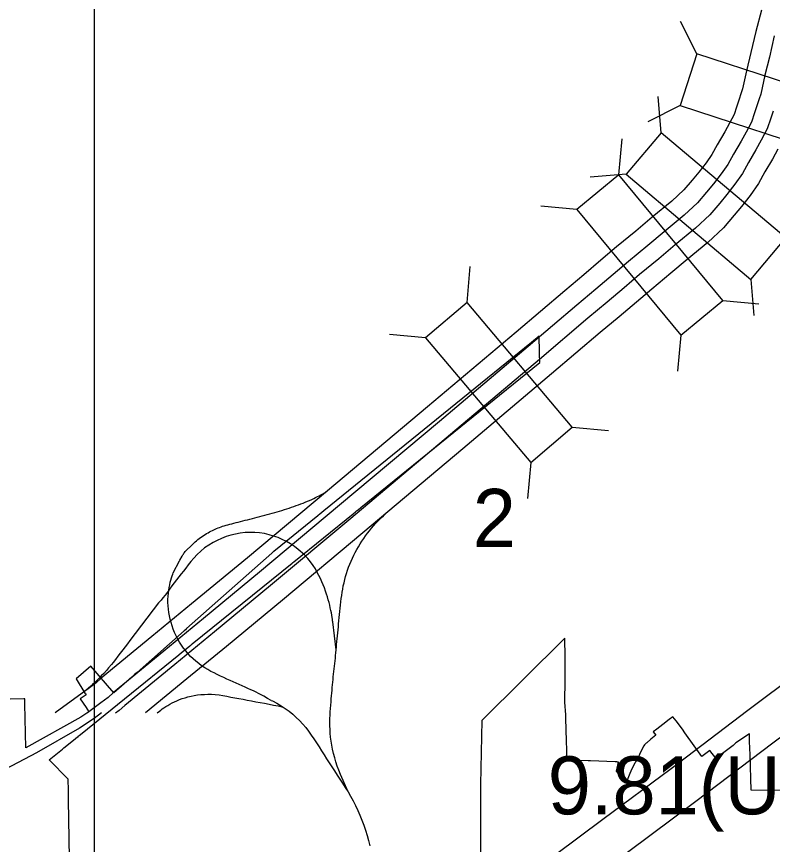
# Model space of a CAD drawing. Extents: x 1127717 to 1741049, y 2026793 to 2244711.
# Drawn here: x 1240828 to 1243581, y 2142172 to 2145187 of the extents above; entities that cross this region are included whole.
import ezdxf

# ---------------------------------------------------------------- set-up
doc = ezdxf.new("R2010")
doc.units = 0
for name, color, linetype in [('10', 7, 'Continuous'), ('15', 7, 'Continuous'), ('20', 7, 'Continuous'), ('30', 7, 'Continuous'), ('58', 7, 'Continuous'), ('6', 7, 'Continuous')]:
    doc.layers.add(name, color=color, linetype=linetype)

msp = doc.modelspace()

# ---------------------------------------------------------------- linework, layer by layer
at = {"layer": '10'}
for points in [[(1241669.2, 2143354.5), (1241677.9, 2143356.8), (1241686.8, 2143359.1), (1241695.7, 2143361.4), (1241704.7, 2143363.7), (1241713.8, 2143366.1), (1241722.8, 2143368.4), (1241731.9, 2143370.8), (1241740.9, 2143373.2), (1241750, 2143375.6), (1241759.1, 2143378), (1241768.1, 2143380.5), (1241777.1, 2143383), (1241786, 2143385.7), (1241794.7, 2143388.5), (1241803.3, 2143391.2), (1241811.9, 2143394), (1241820.5, 2143396.8), (1241829.1, 2143399.8), (1241837.6, 2143402.8), (1241846.1, 2143405.8), (1241854.5, 2143409), (1241862.9, 2143412.1), (1241871.2, 2143415.2), (1241879.4, 2143418.4), (1241887.4, 2143421.6), (1241895.2, 2143425), (1241902.8, 2143428.4), (1241910.1, 2143431.8), (1241917.2, 2143435.3), (1241923.9, 2143438.6), (1241930, 2143441.8), (1241935.6, 2143444.7), (1241956.7, 2143456.5)], [(1241755.7, 2142696.3), (1241742.4, 2142704), (1241729, 2142711.5), (1241718.5, 2142716.7), (1241709.6, 2142721.7), (1241700.4, 2142726.4), (1241690.8, 2142731), (1241680.8, 2142735.5), (1241670.6, 2142740.1), (1241660.2, 2142744.8), (1241649.6, 2142749.5), (1241638.8, 2142754.3), (1241627.9, 2142759.2), (1241616.7, 2142764.1), (1241605.5, 2142769.1), (1241594.1, 2142774.2), (1241582.5, 2142779.5), (1241570.9, 2142784.9), (1241559.2, 2142790.5), (1241547.7, 2142796.3), (1241536, 2142802.3), (1241524.5, 2142808.7), (1241513.2, 2142815.5), (1241502, 2142822.8), (1241491.3, 2142830.7), (1241481, 2142839.1), (1241471.3, 2142847.8), (1241461.9, 2142856.8), (1241453, 2142866.4), (1241444.5, 2142876.4), (1241436.5, 2142886.7), (1241428.9, 2142897.4), (1241421.9, 2142908.5), (1241415.3, 2142919.8), (1241409.2, 2142931.4), (1241403.7, 2142943.3), (1241398.8, 2142955.4), (1241394.5, 2142967.7), (1241390.7, 2142980.1), (1241387.5, 2142992.4), (1241384.8, 2143004.6), (1241382.6, 2143016.8), (1241381, 2143028.8), (1241380, 2143040.8), (1241379.5, 2143052.6), (1241379.5, 2143064.4), (1241380, 2143075.9), (1241380.9, 2143087.1), (1241382.3, 2143097.8), (1241383.9, 2143107.8), (1241385.8, 2143117.4), (1241387.9, 2143126.5), (1241390, 2143134.9), (1241392.2, 2143142.6), (1241394.5, 2143149.6), (1241396.8, 2143155.7), (1241398.9, 2143161), (1241421.1, 2143204.5), (1241422.2, 2143207), (1241431.1, 2143221.9), (1241432.5, 2143224.2), (1241433.9, 2143226.5), (1241435.7, 2143229.2), (1241437.7, 2143232.1), (1241439.9, 2143235.1), (1241442.4, 2143238.3), (1241468.8, 2143264.6), (1241473.4, 2143269.2), (1241478.2, 2143273.7), (1241483, 2143278), (1241488, 2143282.2), (1241493.2, 2143286.2), (1241498.5, 2143290), (1241503.8, 2143293.7), (1241509.2, 2143297.3), (1241514.5, 2143300.7), (1241519.9, 2143304), (1241525.3, 2143307.1), (1241530.6, 2143310), (1241535.9, 2143312.8), (1241541.1, 2143315.4), (1241546.2, 2143317.9), (1241551.3, 2143320.3), (1241556.4, 2143322.5), (1241561.7, 2143324.5), (1241567.1, 2143326.5), (1241572.7, 2143328.5), (1241578.6, 2143330.5), (1241584.7, 2143332.4), (1241591.2, 2143334.3), (1241598, 2143336.1), (1241605, 2143337.9), (1241612.3, 2143339.8), (1241619.9, 2143341.8), (1241627.6, 2143344), (1241635.6, 2143346.1), (1241643.7, 2143348.2), (1241652, 2143350.3), (1241660.5, 2143352.4), (1241669.2, 2143354.5)], [(1242035.1, 2142363.5), (1242007.7, 2142426.9), (1242001.7, 2142441.9), (1241996.2, 2142457.2), (1241991.2, 2142472.6), (1241986.8, 2142487.9), (1241982.8, 2142503.2), (1241979.2, 2142518.3), (1241976.1, 2142533.2), (1241973.7, 2142547.9), (1241971.8, 2142562.5), (1241970.5, 2142576.7), (1241969.7, 2142590.7), (1241969.2, 2142604.1), (1241969.1, 2142617.3), (1241969.2, 2142630.2), (1241969.7, 2142642.9), (1241970.4, 2142655.3), (1241971.3, 2142667.5), (1241972.3, 2142679.4), (1241973.4, 2142691), (1241974.3, 2142702.2), (1241975.2, 2142712.9), (1241976.1, 2142723.2), (1241976.9, 2142733.3), (1241977.8, 2142743.2), (1241978.7, 2142752.9), (1241979.6, 2142762.7), (1241980.6, 2142772.4), (1241981.6, 2142782.1), (1241982.7, 2142791.9), (1241983.8, 2142801.6), (1241984.9, 2142811.4), (1241986, 2142821.2), (1241987, 2142830.9), (1241988, 2142840.7), (1241989, 2142850.6), (1241989.9, 2142860.4), (1241990.8, 2142870.3), (1241991.7, 2142880.2), (1241992.7, 2142890.2), (1241993.6, 2142900.3), (1241994.6, 2142910.6), (1241995.6, 2142921), (1241996.6, 2142931.6), (1241997.7, 2142942.3), (1241998.8, 2142953.1), (1241999.9, 2142964.1), (1242001, 2142975.2), (1242002.2, 2142986.5), (1242003.3, 2142997.8), (1242004.6, 2143009.1), (1242005.8, 2143020.5), (1242007, 2143032.1), (1242008.2, 2143043.7), (1242010.7, 2143067), (1242012.1, 2143078.7), (1242013.8, 2143090.3), (1242015.7, 2143101.9), (1242017.9, 2143113.4), (1242020.5, 2143124.9), (1242023.2, 2143136.3), (1242026.3, 2143147.7), (1242029.7, 2143159.1), (1242033.4, 2143170.3), (1242037.4, 2143181.5), (1242041.7, 2143192.5), (1242046.3, 2143203.4), (1242051.1, 2143214.1), (1242056.1, 2143224.8), (1242061.4, 2143235.3), (1242067, 2143245.8), (1242072.9, 2143256), (1242079, 2143266.1), (1242085.5, 2143276.1), (1242092.2, 2143285.9), (1242099, 2143295.6), (1242106, 2143305.1), (1242113.2, 2143314.3), (1242120.6, 2143323.3), (1242128, 2143332), (1242135.5, 2143340.3), (1242142.7, 2143348), (1242149.9, 2143355.2), (1242157.1, 2143362), (1242164.1, 2143368.4), (1242173.3, 2143377.3)], [(1241991.7, 2142880.2), (1241979.5, 2142982.2), (1241978.9, 2142986.6), (1241978.2, 2142991.9), (1241977.3, 2142998.7), (1241976, 2143006.6), (1241974.5, 2143014.9), (1241972.7, 2143023.8), (1241970.7, 2143033.3), (1241968.4, 2143042.8), (1241965.9, 2143052.7), (1241963.1, 2143062.8), (1241960, 2143073.2), (1241956.6, 2143083.9), (1241952.9, 2143094.7), (1241948.9, 2143105.9), (1241944.3, 2143117.4), (1241939.5, 2143128.7), (1241934.4, 2143139.9), (1241929, 2143151.1), (1241923.1, 2143162.7), (1241916.2, 2143175.2), (1241908, 2143188.2), (1241898.6, 2143201.3), (1241888.3, 2143213.7), (1241876.6, 2143226.2), (1241854, 2143246.5), (1241839.8, 2143257.3), (1241825.4, 2143266.8), (1241810.5, 2143275.3), (1241795.5, 2143282.7), (1241780.2, 2143289.2), (1241764.3, 2143294.9), (1241747.7, 2143299.8), (1241730.5, 2143303.7), (1241713.1, 2143306.4), (1241695.4, 2143308), (1241677.7, 2143308.3), (1241660.1, 2143307.5), (1241642.3, 2143305.5), (1241625.1, 2143302.3), (1241608.3, 2143298.2), (1241591.5, 2143293), (1241574.7, 2143286.6), (1241559, 2143279.3), (1241543.9, 2143271.5), (1241528.5, 2143262.3), (1241513.1, 2143251.6), (1241498.6, 2143239.7), (1241485.6, 2143227.4), (1241473.4, 2143214.7), (1241462.4, 2143201.8), (1241452.8, 2143189.7), (1241444.1, 2143178.3), (1241435.9, 2143167.6), (1241427.6, 2143156.9), (1241419.2, 2143146), (1241410.9, 2143135.1), (1241402.4, 2143124.1), (1241394, 2143113.1), (1241385.5, 2143102.1), (1241377.2, 2143091.2), (1241368.7, 2143080.2), (1241360.7, 2143069.8), (1241354.4, 2143061.9), (1241344.7, 2143051.7), (1241240.9, 2142914.1), (1241232.2, 2142902.8), (1241223.5, 2142891.6), (1241214.7, 2142880.3), (1241205.9, 2142868.9), (1241197.1, 2142857.5), (1241188.2, 2142846), (1241179.4, 2142834.6), (1241173.4, 2142826.9), (1241163.5, 2142815.1), (1241155.3, 2142805.9), (1241145.7, 2142795), (1241136.7, 2142785.5), (1241128.7, 2142777.3), (1241120.3, 2142768.4), (1241111.6, 2142760.2), (1241104.3, 2142753.8), (1241098.5, 2142748.7), (1241088.6, 2142740), (1241076.7, 2142730)], [(1243898.9, 2143085.3), (1243769, 2142912), (1243734.4, 2142862.7), (1243709.9, 2142830.5), (1243698.6, 2142819.4), (1243674.7, 2142797.3), (1243491.4, 2142660.2), (1243211.8, 2142447.8), (1242963, 2142262.3), (1242790.6, 2142134.3), (1242584.6, 2141983.8), (1242522, 2141937.1), (1242493.2, 2141917.6), (1242476.6, 2141902.6), (1242450.7, 2141877.1), (1242424.4, 2141844.8), (1242306.6, 2141708.8), (1242245, 2141634.7), (1242230.2, 2141613.9)], [(1244018.9, 2142995.3), (1243890.4, 2142823.9), (1243855.5, 2142774.2), (1243822.8, 2142731.1), (1243802.2, 2142710.9), (1243771, 2142681.9), (1243581.7, 2142540.4), (1243302, 2142328), (1243052.6, 2142142), (1242879.6, 2142013.5), (1242673.7, 2141863.1), (1242608.9, 2141814.8), (1242585.9, 2141799.2), (1242579.4, 2141793.3), (1242561.8, 2141776), (1242539.3, 2141748.4), (1242421, 2141611.8), (1242363.9, 2141543.1), (1242339.2, 2141508.4), (1242308.1, 2141461.2), (1242275.8, 2141417), (1242253.4, 2141381.2), (1242227.4, 2141356.2)], [(1241340.3, 2142650.7), (1241348.1, 2142657.2), (1241353, 2142661.2), (1241358.6, 2142665.4), (1241364.8, 2142669.7), (1241371.5, 2142674), (1241378.7, 2142678.4), (1241386.4, 2142682.8), (1241394.6, 2142687.2), (1241403.1, 2142691.4), (1241412.1, 2142695.4), (1241421.5, 2142699.3), (1241431.3, 2142702.9), (1241441.6, 2142706.2), (1241452.4, 2142709.2), (1241463.6, 2142711.9), (1241475.2, 2142714.2), (1241487.1, 2142716.2), (1241499.5, 2142717.6), (1241512.1, 2142718.5), (1241525.1, 2142718.9), (1241538.4, 2142718.6), (1241551.9, 2142717.8), (1241565.7, 2142716.2), (1241579.7, 2142714.1), (1241594, 2142711.6), (1241608.4, 2142708.8), (1241623.1, 2142706), (1241638, 2142703.2), (1241653.1, 2142700.4), (1241668.3, 2142697.6), (1241683.8, 2142694.7), (1241699.5, 2142691.8), (1241715.3, 2142688.9), (1241731.5, 2142685.9), (1241747.7, 2142682.9), (1241764.2, 2142679.7), (1241780.6, 2142676.3), (1241799.1, 2142672.2)], [(1241755.7, 2142696.3), (1241760, 2142694.3), (1241776, 2142686.1), (1241791.7, 2142677), (1241806.7, 2142667.3), (1241820.8, 2142657.1), (1241834.2, 2142646.3), (1241846.8, 2142634.8), (1241858.8, 2142622.8), (1241870.2, 2142610.3), (1241881, 2142597.3), (1241891.4, 2142583.9), (1241901.5, 2142570.2), (1241911.1, 2142556.1), (1241920.4, 2142541.7), (1241929.5, 2142527.3), (1241938.6, 2142512.8), (1241947.7, 2142498.2), (1241956.9, 2142483.7), (1241966.4, 2142469.1), (1241976, 2142454.4), (1241985.7, 2142439.6), (1241995.4, 2142424.8), (1242005.3, 2142409.9), (1242015.4, 2142394.8), (1242025.3, 2142379.3), (1242035.1, 2142363.5), (1242044.5, 2142347.3), (1242053.6, 2142330.6), (1242062.2, 2142313.5), (1242070.3, 2142296), (1242078.1, 2142278.3), (1242085.4, 2142260.2), (1242092.1, 2142241.9), (1242098.5, 2142223.4), (1242104.4, 2142204.8), (1242109.8, 2142186), (1242114.7, 2142167.1)]]:
    msp.add_lwpolyline(points, dxfattribs=at)
at = {"layer": '15'}
for points in [[(1243540.2, 2145209.6), (1243519.8, 2145132.9), (1243502.5, 2145055.4), (1243485.7, 2144989.1), (1243471.7, 2144923.2), (1243466.6, 2144908.9), (1243457.9, 2144882.2), (1243450.1, 2144857.1), (1243440.8, 2144830), (1243424.3, 2144798.5), (1243406.7, 2144766.8), (1243379.1, 2144719.6), (1243360.2, 2144684.8), (1243338.7, 2144654.7), (1243312.3, 2144620.4), (1243288.3, 2144591.5), (1243258, 2144555.6), (1243213.8, 2144514.8), (1243142.4, 2144455.8), (1243082.7, 2144405.4), (1243012.7, 2144347.6), (1242956, 2144299.5), (1242893.7, 2144246.7), (1242824.2, 2144188.4), (1242647.2, 2144037.9), (1242324, 2143765.3), (1241960.4, 2143459.6), (1241669.3, 2143215.9), (1241465.4, 2143047.7), (1241320.9, 2142929.1), (1241136.6, 2142777.4), (1241118, 2142760.7), (1241093.8, 2142742.6), (1240969.3, 2142650.9)], [(1243586.6, 2145116.6), (1243569.4, 2145039.5), (1243552.7, 2144973.5), (1243538, 2144904.6), (1243531.7, 2144886.8), (1243523.4, 2144861.4), (1243515.4, 2144835.7), (1243504.1, 2144802.8), (1243484.8, 2144765.8), (1243466.4, 2144732.7), (1243439, 2144685.9), (1243418.6, 2144648.2), (1243393.9, 2144613.7), (1243365.9, 2144577.4), (1243341, 2144547.4), (1243307.8, 2144508.1), (1243259.1, 2144463), (1243186.4, 2144403), (1243126.7, 2144352.7), (1243056.8, 2144294.9), (1243000.5, 2144247.1), (1242938, 2144194.2), (1242868.6, 2144135.9), (1242691.6, 2143985.4), (1242368.3, 2143712.7), (1242004.6, 2143406.9), (1241713.3, 2143163.1), (1241509.1, 2142994.6), (1241364.5, 2142876), (1241181.5, 2142725.3), (1241161.7, 2142707.5), (1241134.7, 2142687.3), (1241086, 2142651.5)], [(1243583, 2144842.4), (1243574.8, 2144816.3), (1243561.7, 2144778), (1243539.8, 2144736.2), (1243520.7, 2144701.7), (1243493.5, 2144655.2), (1243471.7, 2144615), (1243444.1, 2144576.4), (1243414.7, 2144538.3), (1243388.9, 2144507.3), (1243353.1, 2144464.8), (1243300.2, 2144415.9), (1243226.4, 2144355), (1243166.8, 2144304.7), (1243097, 2144247), (1243040.9, 2144199.4), (1242978.3, 2144146.4), (1242908.9, 2144088.2), (1242732, 2143937.7), (1242408.5, 2143664.9), (1242044.8, 2143359.1), (1241753.2, 2143115), (1241548.8, 2142946.4), (1241404.2, 2142827.7), (1241222.3, 2142678), (1241201.4, 2142659.2), (1241189, 2142649.8)], [(1243600.4, 2144703.6), (1243580.4, 2144667.7), (1243553.4, 2144621.4), (1243530.1, 2144578.5), (1243499.3, 2144535.4), (1243468.4, 2144495.4), (1243441.6, 2144463.1), (1243402.9, 2144417.2), (1243345.5, 2144364.1), (1243270.5, 2144302.2), (1243210.9, 2144251.9), (1243141.1, 2144194.3), (1243085.3, 2144146.9), (1243022.6, 2144093.8), (1242953.3, 2144035.7), (1242776.5, 2143885.2), (1242452.8, 2143612.3), (1242089, 2143306.4), (1241797.1, 2143062.1), (1241592.5, 2142893.3), (1241447.8, 2142774.6), (1241297.4, 2142650.7)], [(1241138, 2142650.9), (1241111, 2142631.1), (1241056.9, 2142595.5), (1240901.2, 2142506), (1240717.4, 2142410)]]:
    msp.add_lwpolyline(points, dxfattribs=at)
at = {"layer": '20'}
for p, q in [((1243305.7, 2145051), (1243245.9, 2145168.6)), ((1243175.9, 2144763.9), (1243164.8, 2144895.4)), ((1243244.4, 2144862.7), (1243126.7, 2144802.9)), ((1243021.4, 2144610.4), (1243033.9, 2144741.8)), ((1243048.3, 2144612.5), (1242916.7, 2144601.4)), ((1242868.8, 2144484.3), (1242737.4, 2144496.8)), ((1242468.7, 2144145), (1242479.9, 2144276.6)), ((1243502.3, 2144229.5), (1243513.4, 2144098)), ((1243399.9, 2144152.6), (1243531.3, 2144140.1)), ((1242317.3, 2144017.4), (1242185.8, 2144028.6)), ((1243247.3, 2144026.4), (1243234.8, 2143895)), ((1242851.6, 2143690.9), (1242983.2, 2143679.8)), ((1242700.3, 2143563.3), (1242689.1, 2143431.8))]:
    msp.add_line(p, q, dxfattribs=at)
for points in [[(1243244.4, 2144862.7), (1243809.2, 2144678.7), (1243870.5, 2144867), (1243305.7, 2145051)], [(1243629.9, 2144380.9), (1243175.9, 2144763.9), (1243048.3, 2144612.5), (1243502.3, 2144229.5)], [(1242868.8, 2144484.3), (1243247.3, 2144026.4), (1243399.9, 2144152.6), (1243021.4, 2144610.4)], [(1242317.3, 2144017.4), (1242700.3, 2143563.3), (1242851.6, 2143690.9), (1242468.7, 2144145)]]:
    msp.add_lwpolyline(points, close=True, dxfattribs=at)
at = {"layer": '30'}
msp.add_line((1241111.2, 2151684.2), (1241111.2, 2119636.1), dxfattribs=at)
at = {"layer": '6'}
for points in [[(1241022.2, 2142050.7), (1241017.5, 2142334.7), (1241016.9, 2142372.8), (1241016.8, 2142376.7), (1241016.4, 2142401.4), (1241016.3, 2142405.4), (1241016.3, 2142409.1), (1240946.3, 2142479.8), (1240995.2, 2142519.4), (1241000.7, 2142523.9), (1241035.6, 2142552.1), (1241042.8, 2142558), (1241044.1, 2142559), (1241051.9, 2142565.3), (1241052.4, 2142565.8), (1241059.5, 2142571.5), (1241060.3, 2142572.1), (1241060.5, 2142572.3), (1241221, 2142702.2), (1241419, 2142862.5), (1241429, 2142870.6), (1241457.6, 2142893.7), (1241459.8, 2142895.6), (1241461.1, 2142896.6), (1241461.5, 2142896.9), (1241461.6, 2142897), (1241462, 2142897.3), (1241462.4, 2142897.6), (1241463.7, 2142898.7), (1241464.2, 2142899.1), (1241466.1, 2142900.6), (1241466.4, 2142900.9), (1241467.7, 2142901.9), (1241831.7, 2143196.5), (1241831.9, 2143196.7), (1241832.8, 2143197.5), (1241833.4, 2143197.9), (1241833.9, 2143198.3), (1241834.8, 2143199.1), (1241836.1, 2143200.1), (1241837.3, 2143201.1), (1242053.4, 2143376), (1242062.9, 2143383.7), (1242066.6, 2143386.7), (1242071.9, 2143391), (1242072.9, 2143391.9), (1242082, 2143399.2), (1242733.3, 2143926.4), (1242732.5, 2143959.7), (1242732.5, 2143961.9), (1242732.4, 2143965.3), (1242732.4, 2143967.6), (1242732.3, 2143969.6), (1242732.2, 2143973.8), (1242731.9, 2143987.8), (1242731.8, 2143991.3), (1242731.8, 2143992.9), (1242731.7, 2143994.8), (1242731.6, 2143999.9), (1242731.1, 2144023.2), (1242702.7, 2144000.1), (1241947.5, 2143386.9), (1241940.2, 2143381), (1241939.9, 2143380.8), (1241933, 2143375.2), (1241926.4, 2143369.8), (1241926.2, 2143369.6), (1241925.5, 2143369.1), (1241764.5, 2143238.4), (1241762.9, 2143237.1)], [(1241762.9, 2143237.1), (1241761.9, 2143236.3), (1241761.9, 2143236.2), (1241760.4, 2143235), (1241760.1, 2143234.7), (1241757.8, 2143232.9), (1241447.3, 2142958), (1241447.3, 2142957.9), (1241442.9, 2142954), (1241438.1, 2142949.8), (1241266.8, 2142798.1), (1241259.4, 2142791.5), (1241248.2, 2142781.6), (1241182.6, 2142723.6), (1241099, 2142820.6), (1241045.1, 2142774.5), (1241077.2, 2142723.4), (1241079.1, 2142720.4), (1241081.7, 2142716.2), (1241060.2, 2142702.5), (1241081.2, 2142670.2), (1241085, 2142664.2), (1241091.1, 2142654.8), (1241091.4, 2142654.3), (1241061.6, 2142635.5), (1240861.6, 2142523.6), (1240858.6, 2142684), (1240858.3, 2142701.7), (1240856.3, 2142701.7), (1240854.4, 2142701.6), (1240804.3, 2142701)], [(1242831.4, 2142516.6), (1242830.9, 2142547.9), (1242828, 2142631.2), (1242827.8, 2142643.9), (1242825.1, 2142689.5), (1242825.4, 2142771.2), (1242825.7, 2142873.6), (1242824.8, 2142903.6), (1242824.3, 2142922.6), (1242521.9, 2142623.4), (1242517, 2142389.7), (1242517.6, 2142137.4)], [(1243826.4, 2142365.9), (1243503, 2142369.1), (1243499, 2142498), (1243497.4, 2142547.1), (1243496.9, 2142565.5), (1243496.8, 2142568.7), (1243496.7, 2142571.8), (1243496.6, 2142575), (1243447.3, 2142541.4), (1243444.8, 2142539.1), (1243442.7, 2142537.1), (1243440.5, 2142535.1), (1243437.9, 2142532.6), (1243422.6, 2142521), (1243408.3, 2142510.2), (1243382.1, 2142491.1), (1243376.5, 2142487), (1243374.6, 2142485.6), (1243352.7, 2142513.7), (1243323.5, 2142492.3), (1243261.2, 2142577.9), (1243253.1, 2142591.9), (1243229.7, 2142621.6), (1243218.3, 2142636.1), (1243217.4, 2142637), (1243204, 2142626.4), (1243182, 2142609.1), (1243159.7, 2142591.5), (1243146.8, 2142582.4), (1243155.6, 2142569.3), (1243138.2, 2142554.9), (1243123.1, 2142542.5), (1243120.4, 2142540.3), (1243117, 2142536.6), (1243116.1, 2142535.6), (1243115.2, 2142534.6), (1243111.8, 2142530.9), (1243101.5, 2142510.4), (1243091.3, 2142488.5), (1243082.4, 2142472.2), (1243079.2, 2142467.4), (1243066.8, 2142444.7), (1243048.3, 2142397.6), (1243013, 2142438.3), (1243019.9, 2142471.1), (1243015.9, 2142471.9), (1243013.7, 2142472.3), (1243011.5, 2142472.7), (1243008.2, 2142473.3), (1242917.6, 2142476.3), (1242912, 2142476.5), (1242909.9, 2142476.6), (1242832.2, 2142479.1), (1242831.4, 2142516.6)]]:
    msp.add_lwpolyline(points, dxfattribs=at)

# ---------------------------------------------------------------- texts
at = {"layer": '20'}
msp.add_text('2', height=211.2, dxfattribs=at).set_placement((1242489.4, 2143255.5))
at = {"layer": '58'}
msp.add_text('9.81(U.P.)', height=211.2, dxfattribs=at).set_placement((1242762.5, 2142281.5))

doc.saveas('drawing.dxf')
